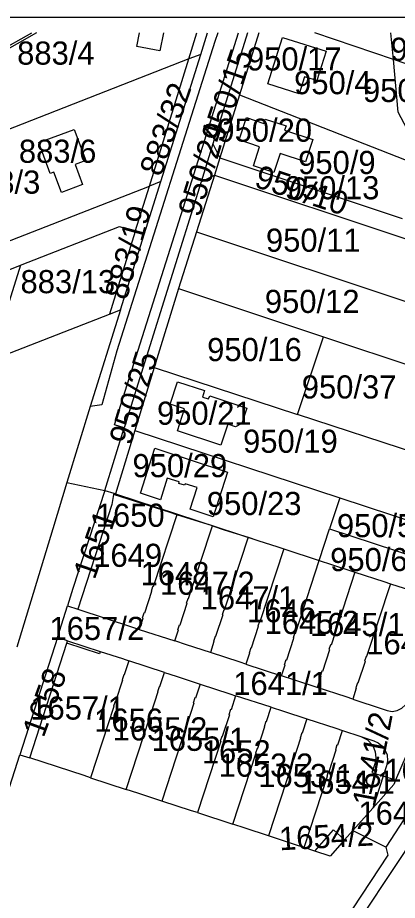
# Model space of a CAD drawing. Extents: x -583889 to -582839, y -1166553 to -1165065.
# Drawn here: x -583111.8 to -582997, y -1165334.9 to -1165067.8 of the extents above; entities that cross this region are included whole.
import ezdxf

# ---------------------------------------------------------------- set-up
doc = ezdxf.new("R2010")
doc.units = 0
for name, color, linetype in [('56', 7, 'Continuous'), ('Popis cest', 7, 'Continuous'), ('Vrstva 2', 7, 'Continuous')]:
    doc.layers.add(name, color=color, linetype=linetype)

msp = doc.modelspace()

# ---------------------------------------------------------------- linework, layer by layer
at = {"layer": '56'}
msp.add_lwpolyline([(-583888.67, -1166552.78), (-582838.67, -1166552.78), (-582838.67, -1165067.78), (-583888.67, -1165067.78), (-583888.67, -1166552.78)], dxfattribs=at)
at = {"layer": 'Vrstva 2'}
for p, q in [((-583182.09, -1165114.62), (-583107.53, -1165072.33)), ((-583106.15, -1165072.33), (-583138.25, -1165090.53)), ((-583060.04, -1165080.27), (-583057.61, -1165072.33)), ((-583056.45, -1165078.88), (-583054.39, -1165072.33)), ((-583042.28, -1165072.33), (-583052.78, -1165105.96)), ((-583038.87, -1165072.33), (-583044.73, -1165091.1)), ((-582998.19, -1165080.46), (-583021.98, -1165072.33)), ((-582998.19, -1165080.46), (-582998.97, -1165072.33)), ((-583060.04, -1165080.27), (-583145.52, -1165113.73)), ((-583071.94, -1165118.73), (-583060.04, -1165080.27)), ((-583068.53, -1165117.4), (-583056.45, -1165078.88)), ((-583056.45, -1165078.88), (-583060.04, -1165080.27)), ((-582989.08, -1165083.58), (-582998.19, -1165080.46)), ((-583044.73, -1165091.1), (-583050.67, -1165110.17)), ((-583044.73, -1165091.1), (-582992.03, -1165111.81)), ((-583052.78, -1165105.96), (-583056.37, -1165117.45)), ((-583052.78, -1165105.96), (-583050.67, -1165110.17)), ((-583050.67, -1165110.17), (-583052.33, -1165115.41)), ((-583050.67, -1165110.17), (-582995.55, -1165128.53)), ((-583052.33, -1165115.41), (-583057.74, -1165132.59)), ((-583056.37, -1165117.45), (-583052.33, -1165115.41)), ((-583052.33, -1165115.41), (-582994.16, -1165134.79)), ((-583080.7, -1165156.18), (-583068.53, -1165117.4)), ((-583068.53, -1165117.4), (-583071.94, -1165118.73)), ((-583157.61, -1165152.25), (-583071.94, -1165118.73)), ((-583076.26, -1165132.5), (-583071.94, -1165118.73)), ((-583076.26, -1165132.5), (-583084.11, -1165157.51)), ((-583057.74, -1165132.59), (-583063.16, -1165149.76)), ((-583057.74, -1165132.59), (-582990.33, -1165155.04)), ((-583137.89, -1165153.24), (-583111.02, -1165142.73)), ((-583111.02, -1165142.73), (-583120.08, -1165171.59)), ((-583063.16, -1165149.76), (-583070.52, -1165173.65)), ((-583063.16, -1165149.76), (-583019.35, -1165164.35)), ((-583120.08, -1165171.59), (-583084.11, -1165157.51)), ((-583080.7, -1165156.18), (-583089.9, -1165185.49)), ((-583084.11, -1165157.51), (-583080.7, -1165156.18)), ((-583027.19, -1165187.87), (-583019.35, -1165164.35)), ((-583019.35, -1165164.35), (-582985.47, -1165175.64)), ((-583070.52, -1165173.65), (-583076.41, -1165192.76)), ((-583070.52, -1165173.65), (-583027.19, -1165187.87)), ((-583089.9, -1165185.49), (-583097.01, -1165208.5)), ((-582983.21, -1165202.31), (-583027.19, -1165187.87)), ((-583085.46, -1165210.84), (-583079.6, -1165191.86)), ((-583076.41, -1165192.76), (-583082.3, -1165211.87)), ((-583076.41, -1165192.76), (-583014.39, -1165213.12)), ((-583097.01, -1165208.5), (-583085.46, -1165210.84)), ((-583085.46, -1165210.84), (-583082.79, -1165211.71)), ((-583082.79, -1165211.71), (-583082.89, -1165212.12)), ((-583082.79, -1165211.71), (-583082.3, -1165211.87)), ((-583082.3, -1165211.87), (-583039.19, -1165225.97)), ((-583014.39, -1165213.12), (-583017.5, -1165222.52)), ((-583014.39, -1165213.12), (-582983.03, -1165223.42)), ((-583052.95, -1165221.61), (-583063.75, -1165218.19)), ((-583020.63, -1165232.04), (-583017.5, -1165222.52)), ((-583017.5, -1165222.52), (-582983.91, -1165233.54)), ((-583042.16, -1165225.03), (-583039.19, -1165225.97)), ((-583031.38, -1165228.52), (-583020.63, -1165232.04)), ((-582999.09, -1165239.08), (-582984.95, -1165243.7)), ((-583099.84, -1165255.32), (-583096.8, -1165245.8)), ((-583096.8, -1165245.8), (-583093.68, -1165246.81)), ((-583075.1, -1165252.89), (-583064.33, -1165256.41)), ((-583099.84, -1165255.32), (-583111.16, -1165290.82)), ((-583108.21, -1165291.77), (-583096.98, -1165257.04)), ((-583096.75, -1165256.33), (-583099.84, -1165255.32)), ((-583096.98, -1165257.04), (-583096.75, -1165256.33)), ((-583096.75, -1165256.33), (-583086.86, -1165259.56)), ((-583067.44, -1165265.91), (-583078.2, -1165262.4)), ((-583042.8, -1165263.45), (-583032.04, -1165266.97)), ((-583035.15, -1165276.47), (-583045.91, -1165272.96)), ((-583013.61, -1165283.51), (-583008.01, -1165285.35)), ((-583000.42, -1165318.79), (-582978.28, -1165284.82)), ((-583111.16, -1165290.82), (-583108.21, -1165291.77)), ((-583001.29, -1165297.28), (-583004.46, -1165306.99)), ((-582997.54, -1165298.5), (-583001.29, -1165297.28)), ((-583089.78, -1165297.8), (-583079.02, -1165301.32)), ((-583004.46, -1165306.99), (-583010.46, -1165313.76)), ((-583057.48, -1165308.36), (-583046.72, -1165311.88)), ((-582987.21, -1165308.59), (-583007.11, -1165338.81)), ((-583010.46, -1165313.76), (-583012.95, -1165316.56)), ((-583010.46, -1165313.76), (-583000.42, -1165318.79)), ((-583021.97, -1165319.97), (-583025.19, -1165318.92))]:
    msp.add_line(p, q, dxfattribs=at)
for points in [[(-583051.35, -1165072.33), (-583052.21, -1165075.04), (-583061.84, -1165105.52), (-583070.03, -1165131.41), (-583081.8, -1165168.62), (-583086.42, -1165184.92), (-583089.9, -1165185.49)], [(-583079.6, -1165191.86), (-583082.58, -1165191.02), (-583055.97, -1165106.96), (-583045.04, -1165072.33)], [(-583067.77, -1165072.33), (-583068.86, -1165077.84), (-583075.75, -1165076.5), (-583074.98, -1165072.41)], [(-583074.98, -1165072.41), (-583075.04, -1165072.33)], [(-583018.54, -1165077.97), (-583021.36, -1165086.84), (-583025.04, -1165085.68), (-583026.7, -1165090.87), (-583036.17, -1165087.85), (-583031.72, -1165073.8), (-583018.54, -1165077.97)], [(-582993.15, -1165103.26), (-582996.72, -1165096.42), (-582998.19, -1165080.46)], [(-583040.56, -1165112.58), (-583038.67, -1165106.86), (-583044.88, -1165104.75), (-583042.67, -1165098.02), (-583037.36, -1165099.76), (-583036.94, -1165098.49), (-583030.68, -1165100.55), (-583031.11, -1165101.82), (-583022.56, -1165104.69), (-583024.83, -1165111.46), (-583032.42, -1165108.92), (-583034.34, -1165114.66), (-583040.56, -1165112.58)], [(-583098.6, -1165120.64), (-583100.87, -1165114.55), (-583102, -1165114.97), (-583105.48, -1165105.59), (-583094.71, -1165101.6), (-583091.22, -1165110.97), (-583094.5, -1165112.18), (-583092.23, -1165118.28), (-583098.6, -1165120.64)], [(-583056.37, -1165117.45), (-583066.15, -1165148.76), (-583079.6, -1165191.86)], [(-583111.02, -1165142.73), (-583081.03, -1165131), (-583076.26, -1165132.5)], [(-583045.92, -1165191.63), (-583048.29, -1165190.84), (-583050.36, -1165197.14), (-583063.52, -1165192.81), (-583061.35, -1165186.19), (-583065.73, -1165184.7), (-583063.54, -1165178.01), (-583055.34, -1165180.64), (-583055.96, -1165182.62), (-583054.1, -1165183.17), (-583053.75, -1165182.24), (-583042.54, -1165185.94), (-583044, -1165190.61), (-583045.92, -1165191.63)], [(-583066.59, -1165207.14), (-583068.66, -1165213.66), (-583074.74, -1165211.65), (-583070.37, -1165198.11), (-583048.33, -1165205.32), (-583052.75, -1165218.84), (-583059.66, -1165216.57), (-583057.58, -1165210), (-583061.22, -1165208.84), (-583061.36, -1165209.27), (-583063.09, -1165208.73), (-583062.95, -1165208.29), (-583066.59, -1165207.14)], [(-583097.01, -1165208.5), (-583101.24, -1165222.44), (-583112.09, -1165258.27)], [(-583085.46, -1165210.84), (-583095.12, -1165240.52), (-583096.8, -1165245.8)], [(-583082.89, -1165212.12), (-583083.36, -1165215.12), (-583093.68, -1165246.81)], [(-583063.75, -1165218.19), (-583065.72, -1165217.56), (-583082.89, -1165212.12)], [(-583063.75, -1165218.19), (-583070.89, -1165240.03), (-583071.03, -1165239.99), (-583071.5, -1165241.41), (-583071.36, -1165241.46), (-583073.5, -1165248.02), (-583073.64, -1165247.97), (-583074.15, -1165249.52), (-583074.01, -1165249.56), (-583075.1, -1165252.89)], [(-583064.33, -1165256.41), (-583063.24, -1165253.08), (-583063.39, -1165253.04), (-583062.88, -1165251.49), (-583062.74, -1165251.54), (-583060.59, -1165244.98), (-583060.74, -1165244.93), (-583060.27, -1165243.51), (-583060.13, -1165243.55), (-583052.95, -1165221.61)], [(-583052.95, -1165221.61), (-583049.42, -1165222.73), (-583042.16, -1165225.03)], [(-583042.16, -1165225.03), (-583049.36, -1165247.07), (-583049.51, -1165247.03), (-583049.97, -1165248.45), (-583049.83, -1165248.5), (-583051.97, -1165255.06), (-583052.12, -1165255.01), (-583052.62, -1165256.56), (-583052.48, -1165256.6), (-583053.56, -1165259.93)], [(-583039.19, -1165225.97), (-583033.14, -1165227.95), (-583031.38, -1165228.52)], [(-583031.38, -1165228.52), (-583038.6, -1165250.59), (-583038.74, -1165250.55), (-583039.21, -1165251.97), (-583039.06, -1165252.02), (-583041.21, -1165258.58), (-583041.35, -1165258.53), (-583041.86, -1165260.08), (-583041.71, -1165260.12), (-583042.8, -1165263.45)], [(-583032.04, -1165266.97), (-583030.95, -1165263.64), (-583031.09, -1165263.6), (-583030.59, -1165262.05), (-583030.44, -1165262.1), (-583028.3, -1165255.54), (-583028.44, -1165255.49), (-583027.98, -1165254.07), (-583027.83, -1165254.11), (-583020.63, -1165232.04)], [(-583020.63, -1165232.04), (-583016.89, -1165233.26), (-583009.85, -1165235.56)], [(-583009.85, -1165235.56), (-583017.07, -1165257.63), (-583017.21, -1165257.59), (-583017.68, -1165259.01), (-583017.54, -1165259.06), (-583019.68, -1165265.62), (-583019.82, -1165265.57), (-583020.33, -1165267.11), (-583020.19, -1165267.16), (-583021.27, -1165270.49)], [(-583009.85, -1165235.56), (-583001.11, -1165238.42), (-582999.09, -1165239.08)], [(-582999.09, -1165239.08), (-583006.31, -1165261.15), (-583006.45, -1165261.11), (-583006.92, -1165262.53), (-583006.77, -1165262.58), (-583008.92, -1165269.14), (-583009.06, -1165269.09), (-583009.56, -1165270.63), (-583009.42, -1165270.68), (-583010.51, -1165274.01)], [(-583093.68, -1165246.81), (-583077.07, -1165252.25), (-583075.1, -1165252.89)], [(-583086.86, -1165259.56), (-583087.09, -1165260.28), (-583096.98, -1165257.04)], [(-583053.56, -1165259.93), (-583060.81, -1165257.56), (-583064.33, -1165256.41)], [(-583086.86, -1165259.56), (-583080.18, -1165261.75), (-583078.2, -1165262.4)], [(-583042.8, -1165263.45), (-583044.56, -1165262.87), (-583053.56, -1165259.93)], [(-583078.2, -1165262.4), (-583079.6, -1165266.67), (-583079.74, -1165266.63), (-583080.25, -1165268.17), (-583080.11, -1165268.22), (-583082.25, -1165274.77), (-583082.39, -1165274.73), (-583082.86, -1165276.15), (-583082.72, -1165276.2), (-583089.78, -1165297.8)], [(-583079.02, -1165301.32), (-583071.95, -1165279.72), (-583072.09, -1165279.67), (-583071.63, -1165278.25), (-583071.49, -1165278.29), (-583069.34, -1165271.74), (-583069.48, -1165271.69), (-583068.98, -1165270.15), (-583068.84, -1165270.19), (-583067.44, -1165265.91)], [(-583067.44, -1165265.91), (-583063.92, -1165267.06), (-583056.67, -1165269.43)], [(-583021.27, -1165270.49), (-583028.31, -1165268.19), (-583032.04, -1165266.97)], [(-583010.51, -1165274.01), (-583001.61, -1165276.92), (-583000.06, -1165277.42), (-582998.56, -1165277.7), (-582997.02, -1165277.49), (-582995.62, -1165276.78), (-582994.54, -1165275.76), (-582993.75, -1165274.23), (-582991.64, -1165267.79), (-582988.32, -1165268.87)], [(-583056.67, -1165269.43), (-583058.07, -1165273.71), (-583058.21, -1165273.66), (-583058.72, -1165275.21), (-583058.58, -1165275.26), (-583060.72, -1165281.81), (-583060.86, -1165281.77), (-583061.33, -1165283.19), (-583061.19, -1165283.24), (-583068.25, -1165304.84)], [(-583056.67, -1165269.43), (-583047.67, -1165272.38), (-583045.91, -1165272.96)], [(-583010.51, -1165274.01), (-583012.53, -1165273.35), (-583021.27, -1165270.49)], [(-583045.91, -1165272.96), (-583047.31, -1165277.23), (-583047.45, -1165277.18), (-583047.96, -1165278.73), (-583047.81, -1165278.77), (-583049.96, -1165285.33), (-583050.1, -1165285.29), (-583050.57, -1165286.71), (-583050.42, -1165286.76), (-583057.48, -1165308.36)], [(-583046.72, -1165311.88), (-583039.66, -1165290.28), (-583039.8, -1165290.23), (-583039.34, -1165288.81), (-583039.19, -1165288.85), (-583037.05, -1165282.29), (-583037.19, -1165282.25), (-583036.69, -1165280.7), (-583036.54, -1165280.75), (-583035.15, -1165276.47)], [(-583035.15, -1165276.47), (-583031.42, -1165277.69), (-583024.38, -1165279.99)], [(-582990.16, -1165276.9), (-582992.4, -1165286.65), (-582997.54, -1165298.5)], [(-583024.38, -1165279.99), (-583025.78, -1165284.27), (-583025.92, -1165284.22), (-583026.43, -1165285.77), (-583026.29, -1165285.81), (-583028.43, -1165292.37), (-583028.57, -1165292.33), (-583029.04, -1165293.75), (-583028.9, -1165293.8), (-583035.96, -1165315.4)], [(-583024.38, -1165279.99), (-583015.64, -1165282.84), (-583013.61, -1165283.51)], [(-583025.19, -1165318.92), (-583018.13, -1165297.32), (-583018.27, -1165297.27), (-583017.81, -1165295.85), (-583017.67, -1165295.89), (-583015.52, -1165289.33), (-583015.66, -1165289.29), (-583015.16, -1165287.74), (-583015.02, -1165287.79), (-583013.61, -1165283.51)], [(-583008.01, -1165285.35), (-583004.1, -1165286.63), (-583002.78, -1165287.23), (-583001.69, -1165288.11), (-583000.76, -1165289.33), (-583000.13, -1165290.91), (-582999.98, -1165292.65), (-583000.28, -1165294.2), (-583001.29, -1165297.28)], [(-583008.01, -1165285.35), (-583006.02, -1165286.36), (-583004.46, -1165288.06), (-583003.68, -1165289.92), (-583003.47, -1165291.82), (-583003.85, -1165293.55), (-583004.7, -1165296.16), (-583001.29, -1165297.28)], [(-583184.72, -1165523.62), (-583182.81, -1165517.68), (-583176.05, -1165496.65), (-583169.59, -1165475.46), (-583156.46, -1165434.65), (-583140.6, -1165385.28), (-583126.45, -1165339.09), (-583115, -1165302.85), (-583111.16, -1165290.82)], [(-583089.78, -1165297.8), (-583091.75, -1165297.16), (-583108.21, -1165291.77)], [(-582997.54, -1165298.5), (-582998.11, -1165299.82), (-583004.46, -1165306.99)], [(-583068.25, -1165304.84), (-583075.5, -1165302.47), (-583079.02, -1165301.32)], [(-583057.48, -1165308.36), (-583059.24, -1165307.78), (-583068.25, -1165304.84)], [(-583035.96, -1165315.4), (-583042.99, -1165313.1), (-583046.72, -1165311.88)], [(-583025.19, -1165318.92), (-583027.21, -1165318.26), (-583035.96, -1165315.4)], [(-583021.97, -1165319.97), (-583016.31, -1165313.58), (-583012.95, -1165316.56)], [(-583150.03, -1165547.02), (-583146.45, -1165545.26), (-583081.48, -1165445.65), (-583060.78, -1165413.9), (-582999.79, -1165321.21), (-583000.42, -1165318.79)], [(-583012.95, -1165316.56), (-583017.31, -1165321.49), (-583021.97, -1165319.97)]]:
    msp.add_lwpolyline(points, dxfattribs=at)

# ---------------------------------------------------------------- texts
at = {"layer": 'Popis cest'}
for s, p in [('883/4', (-583112, -1165082)), ('950/14', (-582999.09, -1165080.84)), ('950/17', (-583042.5, -1165083.77)), ('950/4', (-583028.23, -1165090.95)), ('950/5', (-583007.4, -1165093.31)), ('950/20', (-583051.43, -1165105.33)), ('883/6', (-583111.47, -1165111.7)), ('950/9', (-583027.01, -1165115.1)), ('883/3', (-583128.41, -1165121.04)), ('950/13', (-583031.07, -1165122.75)), ('950/11', (-583036.75, -1165138.62)), ('883/13', (-583110.98, -1165151.17)), ('950/12', (-583037.08, -1165157.15)), ('950/16', (-583054.53, -1165171.72)), ('950/37', (-583025.91, -1165183.03)), ('950/21', (-583069.7, -1165190.98)), ('950/19', (-583043.66, -1165199.46)), ('950/29', (-583077.11, -1165206.84)), ('950/23', (-583054.63, -1165218.3)), ('1650', (-583088.22, -1165221.86)), ('950/59', (-583015.29, -1165225)), ('1649', (-583088.99, -1165233.98)), ('950/60', (-583017.32, -1165235.27)), ('1648', (-583074.68, -1165239.53)), ('1647/2', (-583068.79, -1165242.43)), ('1647/1', (-583056.49, -1165246.85)), ('1646', (-583042.46, -1165250.76)), ('1657/2', (-583102.21, -1165256.11)), ('1645/2', (-583037.15, -1165254.29)), ('1645/1', (-583023.47, -1165254.92)), ('1643', (-583006.41, -1165260.47)), ('1641/1', (-583046.64, -1165272.76)), ('1657/1', (-583108.03, -1165280.2)), ('1656', (-583088.7, -1165283.86)), ('1655/2', (-583083.13, -1165286.51)), ('1655/1', (-583071.35, -1165289.66)), ('1652', (-583056.14, -1165293.44)), ('1653/2', (-583051.1, -1165297.48)), ('1639', (-583000.96, -1165299.02)), ('1653/1', (-583039.06, -1165300.63)), ('1654/1', (-583026.44, -1165302.65)), ('1640', (-583008.79, -1165312.01))]:
    msp.add_text(s, height=7, dxfattribs=at).set_placement(p)
for s, rotation, p in [('950/15', 71, (-583049.86, -1165105.93)), ('883/32', 71, (-583068.51, -1165116.15)), ('950/24', 73, (-583056.83, -1165128.44)), ('950/10', 342, (-583040.6, -1165118.87)), ('883/19', 75, (-583078.85, -1165153.51)), ('950/25', 73, (-583077.64, -1165197.48)), ('1651', 71, (-583088.55, -1165238.08)), ('1658', 70, (-583104, -1165285.91)), ('1641/2', 79, (-583003.83, -1165306.86)), ('1654/2', 3, (-583032.62, -1165319.77))]:
    msp.add_text(s, height=7, rotation=rotation, dxfattribs=at).set_placement(p)

doc.saveas('drawing.dxf')
